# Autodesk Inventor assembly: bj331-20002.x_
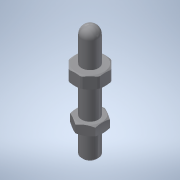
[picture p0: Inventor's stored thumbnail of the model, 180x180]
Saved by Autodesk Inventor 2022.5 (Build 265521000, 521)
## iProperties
Part Number: bj331-20002.x_
Material: 一般
Document SubType Name: Assembly
Designer: ImaoCorp
Sending System: SOLIDWORKS 2017-2017317
MC: AMD64
MC_MODEL: Intel64 Family 6 Model 60 Stepping 3, GenuineIntel
OS: Windows_NT
FRU: Parasolid Version 29.0, build 201,  4-17-2017
FORMAT: text
GUISE: transmit
KEY: bj331-20002
FILE: bj331-20002.x_t
DATE: Fri Mar 15 10:14:13 2019
Author: ImaoCorp
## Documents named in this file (3)
- X:\14_SW2022-Inv2022\00_全2023-1023新製品(TCC)まで\b\bj331-20002\BJ331-20002.iam
- X:\14_SW2022-Inv2022\00_全2023-1023新製品(TCC)まで\b\bj331-20002\bj331-20002_01.ipt
- X:\14_SW2022-Inv2022\00_全2023-1023新製品(TCC)まで\b\bj331-20002\bj331-20002_02.ipt
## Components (2 placed, 2 different names)
1. bj331-20002_01
2. bj331-20002_02
